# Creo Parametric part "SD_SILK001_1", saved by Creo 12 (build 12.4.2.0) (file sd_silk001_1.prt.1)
Units: Custom; MM, KILOGRAM, SECS

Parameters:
  PTC_WM_ITERATION = "0"
  PTC_WM_VERSION = "-.0"
  PTC_WM_LIFECYCLE_STATE = "In Work"
  PTC_WM_LIFECYCLE = "MO_CADDocument"
  PTC_WM_CREATED_BY = "Maximilian Roepper (Z0017RMS: MO)"
  PTC_WM_CREATED_ON = "18-Sep-26 11:36:42 AM"
  PTC_WM_MODIFIED_BY = "Maximilian Roepper (Z0017RMS: MO)"
  PTC_WM_MODIFIED_ON = "18-Sep-26 11:36:46 AM"
  PDMLINKNUMBER = "PDM000071454867"
  PTC_WM_NAME = "sd_silk001_1.prt"
  PTC_WM_NUMBER = "PDM000071454867"

Other parameters: WEIGHT, WEIGHT_FACTOR, WEIGHT_ADD, _MASS_TEMP, _DIFF_TEMP, MC_ERRORS, SUPPLIER

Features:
  1. coordinate system
  2. datum plane "PRT_YZ"
  3. datum plane "PRT_XY"
  4. datum plane "PRT_XZ"
  5. coordinate system
  6. datum axis
  7. datum axis
  8. datum axis
  9. coordinate system
  10. imported feature

Other named items: PRT, SIEMENS_MO, DRW_VIEW_ORG, PRT_X, PRT_Y, PRT_Z, CS0, ROUGH_GROB

Layers: 00_STD_CSYS-KSYS, 01_STD_PLANES-EBENEN, 02_STD_AXES-ACHSEN, 03_STD_CSYS-KSYS, 24_IMPORT_FEAT-IMPORT_KE

Surfaces: 14 plane, 4 cylinder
